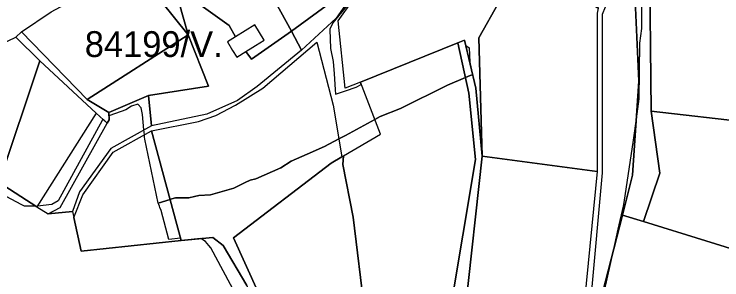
# Model space of a CAD drawing. Extents: x -477304 to -465429, y -1159113 to -1149210.
# Drawn here: x -472801 to -472389, y -1154042.9 to -1153888.3 of the extents above; entities that cross this region are included whole.
import ezdxf

# ---------------------------------------------------------------- set-up
doc = ezdxf.new("R2010")
doc.units = 0
for name, color, linetype in [('BPEJ_s', 7, 'Continuous'), ('orna_s', 7, 'Continuous'), ('PUPFL_s', 7, 'Continuous'), ('trav_porost_s', 7, 'Continuous')]:
    doc.layers.add(name, color=color, linetype=linetype)

msp = doc.modelspace()

# ---------------------------------------------------------------- linework, layer by layer
at = {"layer": 'BPEJ_s'}
for points in [[(-472457.47, -1154049.95), (-472452.3, -1154026.77), (-472449.32, -1154013.41), (-472446.32, -1154000), (-472445.81, -1153997.89), (-472440.41, -1153961.59), (-472438.69, -1153949.12), (-472437.1, -1153937.52), (-472436.67, -1153905.22), (-472435.61, -1153896.72), (-472435.79, -1153868.26)], [(-472457.47, -1154049.95), (-472452.3, -1154026.77), (-472449.32, -1154013.41), (-472446.32, -1154000), (-472445.81, -1153997.89), (-472440.41, -1153961.59), (-472438.69, -1153949.12), (-472437.1, -1153937.52), (-472436.67, -1153905.22), (-472435.61, -1153896.72), (-472435.79, -1153868.26)], [(-472605.75, -1153881.49), (-472615.54, -1153893.41), (-472617.24, -1153897.02), (-472617.23, -1153897.2), (-472616.81, -1153908.3), (-472615.32, -1153915.96), (-472614.76, -1153923.05), (-472614.05, -1153932.13), (-472613.83, -1153934.83), (-472612.13, -1153934.26), (-472608.1, -1153932.91), (-472601.92, -1153930.85), (-472598.87, -1153929.33), (-472599.42, -1153927.91), (-472542.68, -1153905.09), (-472538.77, -1153903.52), (-472538.04, -1153906.63), (-472536.17, -1153907.87), (-472535.77, -1153916.32), (-472534.07, -1153923.56), (-472535.41, -1153924.04), (-472538.29, -1153925.24), (-472548.72, -1153929.58), (-472575.96, -1153943.2), (-472587.87, -1153947.88), (-472591.01, -1153949.57), (-472608.17, -1153958.83), (-472612, -1153960.89), (-472620.22, -1153965.32), (-472630.46, -1153969.78), (-472639.79, -1153973.84), (-472645.75, -1153977.67), (-472660.22, -1153984.05), (-472663.62, -1153984.9), (-472666.43, -1153986.3), (-472672.99, -1153989.58), (-472686.6, -1153993.41), (-472693.41, -1153993.84), (-472696.03, -1153994.4), (-472699.37, -1153995.11), (-472707.03, -1153995.11), (-472709.25, -1153995.79), (-472710.22, -1153996.08), (-472717.13, -1153998.17), (-472724.91, -1153961.07), (-472725.01, -1153959.84), (-472725.13, -1153958.48), (-472725.26, -1153957.02), (-472725.39, -1153955.63), (-472726.18, -1153946.6), (-472727.03, -1153942.77), (-472728.81, -1153940.79), (-472728.95, -1153940.64), (-472732.57, -1153941.92), (-472735.97, -1153944.05), (-472745.33, -1153947.24), (-472745.76, -1153947.53), (-472745.63, -1153949.86), (-472746.73, -1153951.82), (-472749.02, -1153949.7), (-472749.8, -1153950.22), (-472775.33, -1153996.82), (-472778.95, -1153999.02), (-472787.39, -1153999.93), (-472787.72, -1154000.44), (-472788.41, -1154000), (-472795.01, -1154000), (-472796.43, -1153999.26), (-472811.59, -1153991.29)], [(-472605.75, -1153881.49), (-472615.54, -1153893.41), (-472617.24, -1153897.02), (-472617.23, -1153897.2), (-472616.81, -1153908.3), (-472615.32, -1153915.96)], [(-472615.32, -1153915.96), (-472614.76, -1153923.05), (-472614.05, -1153932.13), (-472613.83, -1153934.83), (-472612.13, -1153934.26), (-472608.1, -1153932.91), (-472601.92, -1153930.85), (-472598.87, -1153929.33), (-472599.42, -1153927.91), (-472542.68, -1153905.09), (-472538.77, -1153903.52), (-472538.04, -1153906.63), (-472536.17, -1153907.87), (-472535.77, -1153916.32), (-472534.07, -1153923.56), (-472532.25, -1153931.35), (-472528.59, -1153971.02), (-472538.45, -1154060.94)], [(-472667.84, -1154059.04), (-472686.56, -1154024.17), (-472687.68, -1154022.8), (-472689.53, -1154020.55), (-472692.22, -1154018.87), (-472703.7, -1154020.01), (-472704.1, -1154018.56), (-472710.95, -1154019.43), (-472715.47, -1154002.48), (-472716.11, -1154000.78), (-472716.41, -1154000), (-472716.75, -1153999.13), (-472717.13, -1153998.17), (-472710.22, -1153996.08), (-472709.25, -1153995.79), (-472707.03, -1153995.11), (-472699.37, -1153995.11), (-472696.03, -1153994.4), (-472693.41, -1153993.84), (-472686.6, -1153993.41), (-472672.99, -1153989.58), (-472666.43, -1153986.3), (-472663.62, -1153984.9), (-472660.22, -1153984.05), (-472645.75, -1153977.67), (-472639.79, -1153973.84), (-472630.46, -1153969.78), (-472620.22, -1153965.32), (-472612, -1153960.89), (-472608.17, -1153958.83), (-472591.01, -1153949.57), (-472587.87, -1153947.88), (-472575.96, -1153943.2), (-472548.72, -1153929.58), (-472538.29, -1153925.24), (-472535.41, -1153924.04), (-472534.07, -1153923.56), (-472532.25, -1153931.35), (-472528.59, -1153971.02), (-472538.45, -1154060.94)], [(-472667.84, -1154059.04), (-472686.56, -1154024.17), (-472687.68, -1154022.8), (-472689.53, -1154020.55), (-472692.22, -1154018.87), (-472703.7, -1154020.01), (-472704.1, -1154018.56), (-472710.95, -1154019.43), (-472715.47, -1154002.48), (-472716.11, -1154000.78), (-472716.41, -1154000), (-472716.75, -1153999.13), (-472717.13, -1153998.17), (-472724.91, -1153961.07), (-472725.01, -1153959.84), (-472725.13, -1153958.48), (-472725.26, -1153957.02), (-472725.39, -1153955.63), (-472726.18, -1153946.6), (-472727.03, -1153942.77), (-472728.81, -1153940.79), (-472728.95, -1153940.64), (-472732.57, -1153941.92), (-472735.97, -1153944.05), (-472745.33, -1153947.24), (-472745.76, -1153947.53), (-472745.63, -1153949.86), (-472746.73, -1153951.82), (-472749.02, -1153949.7), (-472749.8, -1153950.22), (-472775.33, -1153996.82), (-472778.95, -1153999.02), (-472787.39, -1153999.93), (-472787.72, -1154000.44), (-472788.41, -1154000), (-472795.01, -1154000), (-472796.43, -1153999.26), (-472811.59, -1153991.29)]]:
    msp.add_lwpolyline(points, dxfattribs=at)
at = {"layer": 'orna_s'}
msp.add_lwpolyline([(-472827.26, -1153988.46), (-472838.92, -1153957.74), (-472853.13, -1153949.74), (-472853.4, -1153914.56), (-472836.18, -1153919.04), (-472799.95, -1153901.78), (-472786, -1153915.46), (-472809.81, -1153986.28)], close=True, dxfattribs=at)
at = {"layer": 'PUPFL_s'}
for points in [[(-472397.97, -1153818.59), (-472406.08, -1153787.93), (-472394.57, -1153785.31), (-472385.29, -1153765.96), (-472383.1, -1153735.59), (-472375.15, -1153737.64), (-472373.8, -1153744.48), (-472371.85, -1153753.62), (-472350.81, -1153807.4), (-472346.26, -1153849.87), (-472338.31, -1153916.68), (-472341.44, -1153961.2), (-472343.16, -1153985.65), (-472344.38, -1153988.72), (-472348.21, -1153964.64), (-472372.57, -1153951.36), (-472430.2, -1153944.84), (-472431.01, -1153851.08), (-472431.2, -1153846.71), (-472404.32, -1153843.6)], [(-472524.56, -1153820.21), (-472517.61, -1153812.6), (-472511.45, -1153801.92), (-472512.56, -1153771.67), (-472511.16, -1153771.61), (-472508.21, -1153780.04), (-472495.68, -1153795.45), (-472486.68, -1153813.03), (-472480.05, -1153832.63), (-472461.02, -1153884.76), (-472506.76, -1153859.99), (-472530.36, -1153902.1), (-472528.59, -1153971.02), (-472532.25, -1153931.35), (-472538.77, -1153903.52), (-472542.68, -1153905.09), (-472599.42, -1153927.91), (-472608.25, -1153931.46), (-472612.3, -1153892.29), (-472603.96, -1153880.54), (-472544.73, -1153837.26)], [(-472721.07, -1153841.8), (-472707.67, -1153872.13), (-472699.71, -1153900.35), (-472730.8, -1153861.6), (-472759.76, -1153876.31), (-472764.06, -1153860.99), (-472761.02, -1153854.73), (-472761.61, -1153852.29)], [(-472439.98, -1153867.43), (-472431.01, -1153851.08), (-472430.2, -1153944.84), (-472425.14, -1153980.83), (-472434.57, -1154008.93), (-472446.75, -1154005.15), (-472440.92, -1153982.01), (-472437.22, -1153927.39)], [(-472461.62, -1153887.74), (-472461.62, -1153979.81), (-472528.59, -1153971.02), (-472530.36, -1153902.1), (-472506.76, -1153859.99), (-472461.02, -1153884.76)], [(-472458.42, -1153888.26), (-472456.78, -1153884.15), (-472439.98, -1153867.43), (-472437.22, -1153927.39), (-472440.92, -1153982.01), (-472446.75, -1154005.15), (-472458.38, -1154050.48), (-472455.38, -1154092.67), (-472452.22, -1154169.89), (-472458.83, -1154198.7), (-472462.78, -1154216.95), (-472453.33, -1154261.75), (-472462.8, -1154283.06), (-472506.01, -1154292.72), (-472517.7, -1154200.33), (-472513.63, -1154180.72), (-472530.52, -1154106.09), (-472468.28, -1154095.1), (-472465.12, -1154094.54), (-472465.12, -1154053.36), (-472458.54, -1153980.69)], [(-472721.1, -1153953.24), (-472744.69, -1153966.39), (-472762.84, -1153991.73), (-472767.03, -1154003.2), (-472781.1, -1154004.49), (-472774.14, -1154000.69), (-472746.73, -1153951.82), (-472745.63, -1153949.86), (-472745.88, -1153945.54), (-472722.68, -1153935.73)], [(-472434.57, -1154008.93), (-472425.14, -1153980.83), (-472430.2, -1153944.84), (-472372.57, -1153951.36), (-472348.21, -1153964.64), (-472344.38, -1153988.72), (-472362.09, -1154031.45)], [(-472721.09, -1153956.22), (-472703.7, -1154020.01), (-472762.01, -1154026.14), (-472766.27, -1154006.69), (-472760.93, -1153993.38), (-472743.35, -1153968.66)], [(-472530.52, -1154106.09), (-472538.45, -1154060.94), (-472528.59, -1153971.02), (-472461.62, -1153979.81), (-472468.89, -1154054.81), (-472468.28, -1154095.1)], [(-472434.57, -1154008.93), (-472362.09, -1154031.45), (-472335.92, -1153986.24), (-472335.63, -1154034.49), (-472333.49, -1154058.22), (-472394.38, -1154075.28), (-472455.38, -1154092.67), (-472458.38, -1154050.48), (-472446.75, -1154005.15)]]:
    msp.add_lwpolyline(points, close=True, dxfattribs=at)
msp.add_lwpolyline([(-472809.81, -1153986.28), (-472787.72, -1154000.44), (-472781.1, -1154004.49), (-472767.03, -1154003.2), (-472766.27, -1154006.69), (-472762.01, -1154026.14), (-472703.7, -1154020.01), (-472685.24, -1154018.18), (-472679.32, -1154022.97), (-472665.52, -1154046.23), (-472657.33, -1154069.24), (-472635.34, -1154110.22), (-472635.02, -1154127.99), (-472638.86, -1154149.74), (-472618.01, -1154173.32), (-472618.34, -1154179.49), (-472622.78, -1154237.39), (-472623.07, -1154248.49), (-472633.5, -1154412.68), (-472635.69, -1154475.83), (-472639.66, -1154532.36), (-472678.01, -1154544.18), (-472718.68, -1154550.96), (-472836.02, -1154538.48)], dxfattribs=at)
at = {"layer": 'trav_porost_s'}
for points in [[(-472687.16, -1153808.83), (-472684.31, -1153814.4), (-472666.75, -1153848.5), (-472657.14, -1153866.1), (-472639.56, -1153898.29), (-472662.79, -1153914.48), (-472666.03, -1153910.04), (-472662.05, -1153907.56), (-472660.45, -1153906.56), (-472655.44, -1153903.44), (-472660.95, -1153894.6), (-472672.05, -1153901.52), (-472675.87, -1153895.02), (-472707.67, -1153872.13), (-472721.07, -1153841.8), (-472703.16, -1153833.72), (-472687.8, -1153817.45)], [(-472542.53, -1153818.64), (-472538.57, -1153828.83), (-472556.12, -1153842.86), (-472595.06, -1153870), (-472605.3, -1153878.86), (-472613.58, -1153890.75), (-472633.67, -1153909.26), (-472639.56, -1153898.29), (-472609.25, -1153875.86), (-472619.19, -1153853.32), (-472614.39, -1153851.15)], [(-472609.25, -1153875.86), (-472639.56, -1153898.29), (-472657.14, -1153866.1), (-472619.19, -1153853.32)], [(-472699.71, -1153900.35), (-472758.4, -1153938.06), (-472796.62, -1153898.64), (-472779.34, -1153886.93), (-472759.76, -1153876.31), (-472730.8, -1153861.6)], [(-472721.1, -1153953.24), (-472722.68, -1153935.73), (-472687.88, -1153930.28), (-472699.71, -1153900.35), (-472707.67, -1153872.13), (-472675.87, -1153895.02), (-472672.05, -1153901.52), (-472676.84, -1153904.5), (-472673.77, -1153909.42), (-472671.33, -1153913.34), (-472666.03, -1153910.04), (-472662.79, -1153914.48), (-472639.56, -1153898.29), (-472633.67, -1153909.26), (-472659.41, -1153930.45), (-472670.92, -1153938.53), (-472688.86, -1153946.45)], [(-472796.62, -1153898.64), (-472758.4, -1153938.06), (-472745.88, -1153945.54), (-472745.63, -1153949.86), (-472746.73, -1153951.82), (-472753.13, -1153945.89), (-472786, -1153915.46), (-472799.95, -1153901.78)], [(-472687.88, -1153930.28), (-472722.68, -1153935.73), (-472745.88, -1153945.54), (-472758.4, -1153938.06), (-472699.71, -1153900.35)], [(-472609.2, -1153970.72), (-472587.7, -1153958.11), (-472599.42, -1153927.91), (-472542.68, -1153905.09), (-472536.32, -1153934.3), (-472532.33, -1153972.86), (-472547.08, -1154060.89), (-472541.57, -1154078.78), (-472537.98, -1154103.11), (-472545.36, -1154106.84), (-472544.23, -1154111.56), (-472534.13, -1154107.04), (-472525.05, -1154144.76), (-472572.62, -1154163.71), (-472573.26, -1154160.94), (-472582.03, -1154129.27), (-472589.55, -1154097.38), (-472596.73, -1154062.16), (-472603.59, -1154006.47), (-472609.63, -1153975.68)], [(-472538.77, -1153903.52), (-472532.25, -1153931.35), (-472528.59, -1153971.02), (-472538.45, -1154060.94), (-472530.52, -1154106.09), (-472513.63, -1154180.72), (-472525.05, -1154144.76), (-472534.13, -1154107.04), (-472544.23, -1154111.56), (-472545.36, -1154106.84), (-472537.98, -1154103.11), (-472541.57, -1154078.78), (-472547.08, -1154060.89), (-472532.33, -1153972.86), (-472536.32, -1153934.3), (-472542.68, -1153905.09)], [(-472787.72, -1154000.44), (-472809.81, -1153986.28), (-472786, -1153915.46), (-472753.13, -1153945.89)]]:
    msp.add_lwpolyline(points, close=True, dxfattribs=at)
for points in [[(-472665.52, -1154046.23), (-472679.32, -1154022.97), (-472685.24, -1154018.18), (-472703.7, -1154020.01), (-472721.09, -1153956.22), (-472693.68, -1153950.83), (-472683.54, -1153947.33), (-472672.04, -1153941.24), (-472656.29, -1153931.38), (-472624.69, -1153904.62), (-472615.3, -1153941.34), (-472610.24, -1153971.33), (-472616.5, -1153975), (-472673.27, -1154018.5), (-472651.5, -1154066.33)], [(-472651.5, -1154066.33), (-472673.27, -1154018.5), (-472616.5, -1153975), (-472610.24, -1153971.33), (-472609.2, -1153970.72), (-472609.63, -1153975.68), (-472603.59, -1154006.47), (-472596.73, -1154062.16)]]:
    msp.add_lwpolyline(points, dxfattribs=at)

# ---------------------------------------------------------------- texts
at = {"layer": 'BPEJ_s'}
msp.add_text('84199/V.', height=15, dxfattribs=at).set_placement((-472759.85, -1153913.24))

doc.saveas('drawing.dxf')
